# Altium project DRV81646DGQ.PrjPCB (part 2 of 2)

## Sheet DRV81646DGQ.SchDoc: DRV81646PWP
size 431 x 279 mm; VersionControl_RevNumber: 1; Date: Not shown in title block; ApprovedBy: Not shown in title block; CheckedBy: Not shown in title block; Author: Not shown in title block; CompanyName: Not shown in title block; DrawnBy: Mojtaba Afshar; Engineer: Not shown in title block; Organization: Not shown in title block; Address1: Not shown in title block; Address2: Not shown in title block; Address3: Not shown in title block; Address4: Not shown in title block; DocumentNumber: 1; Revision: 1; SheetNumber: 3; SheetTotal: 5; PageSetup: Record=PageOptions¦CenterHorizontal=True¦CenterVertical=True¦PrintScale=1.00¦XCorrection=1.00¦YCorrection=1.00¦PrintKind=0¦BorderSize=5000000¦LeftOffset=0¦BottomOffset=0¦Orientation=2¦PaperLength=1000¦PaperWidth=1000¦Scale=100¦PaperSource=15¦PrintQuality=600¦MediaType=1¦DitherType=10¦PaperKind=Letter¦PrintScaleMode=1; VersionControl_ProjFolderRevNumber: 1; VersionControl_RevNumberShort: 1; VersionControl_ProjFolderRevNumberShort: 1
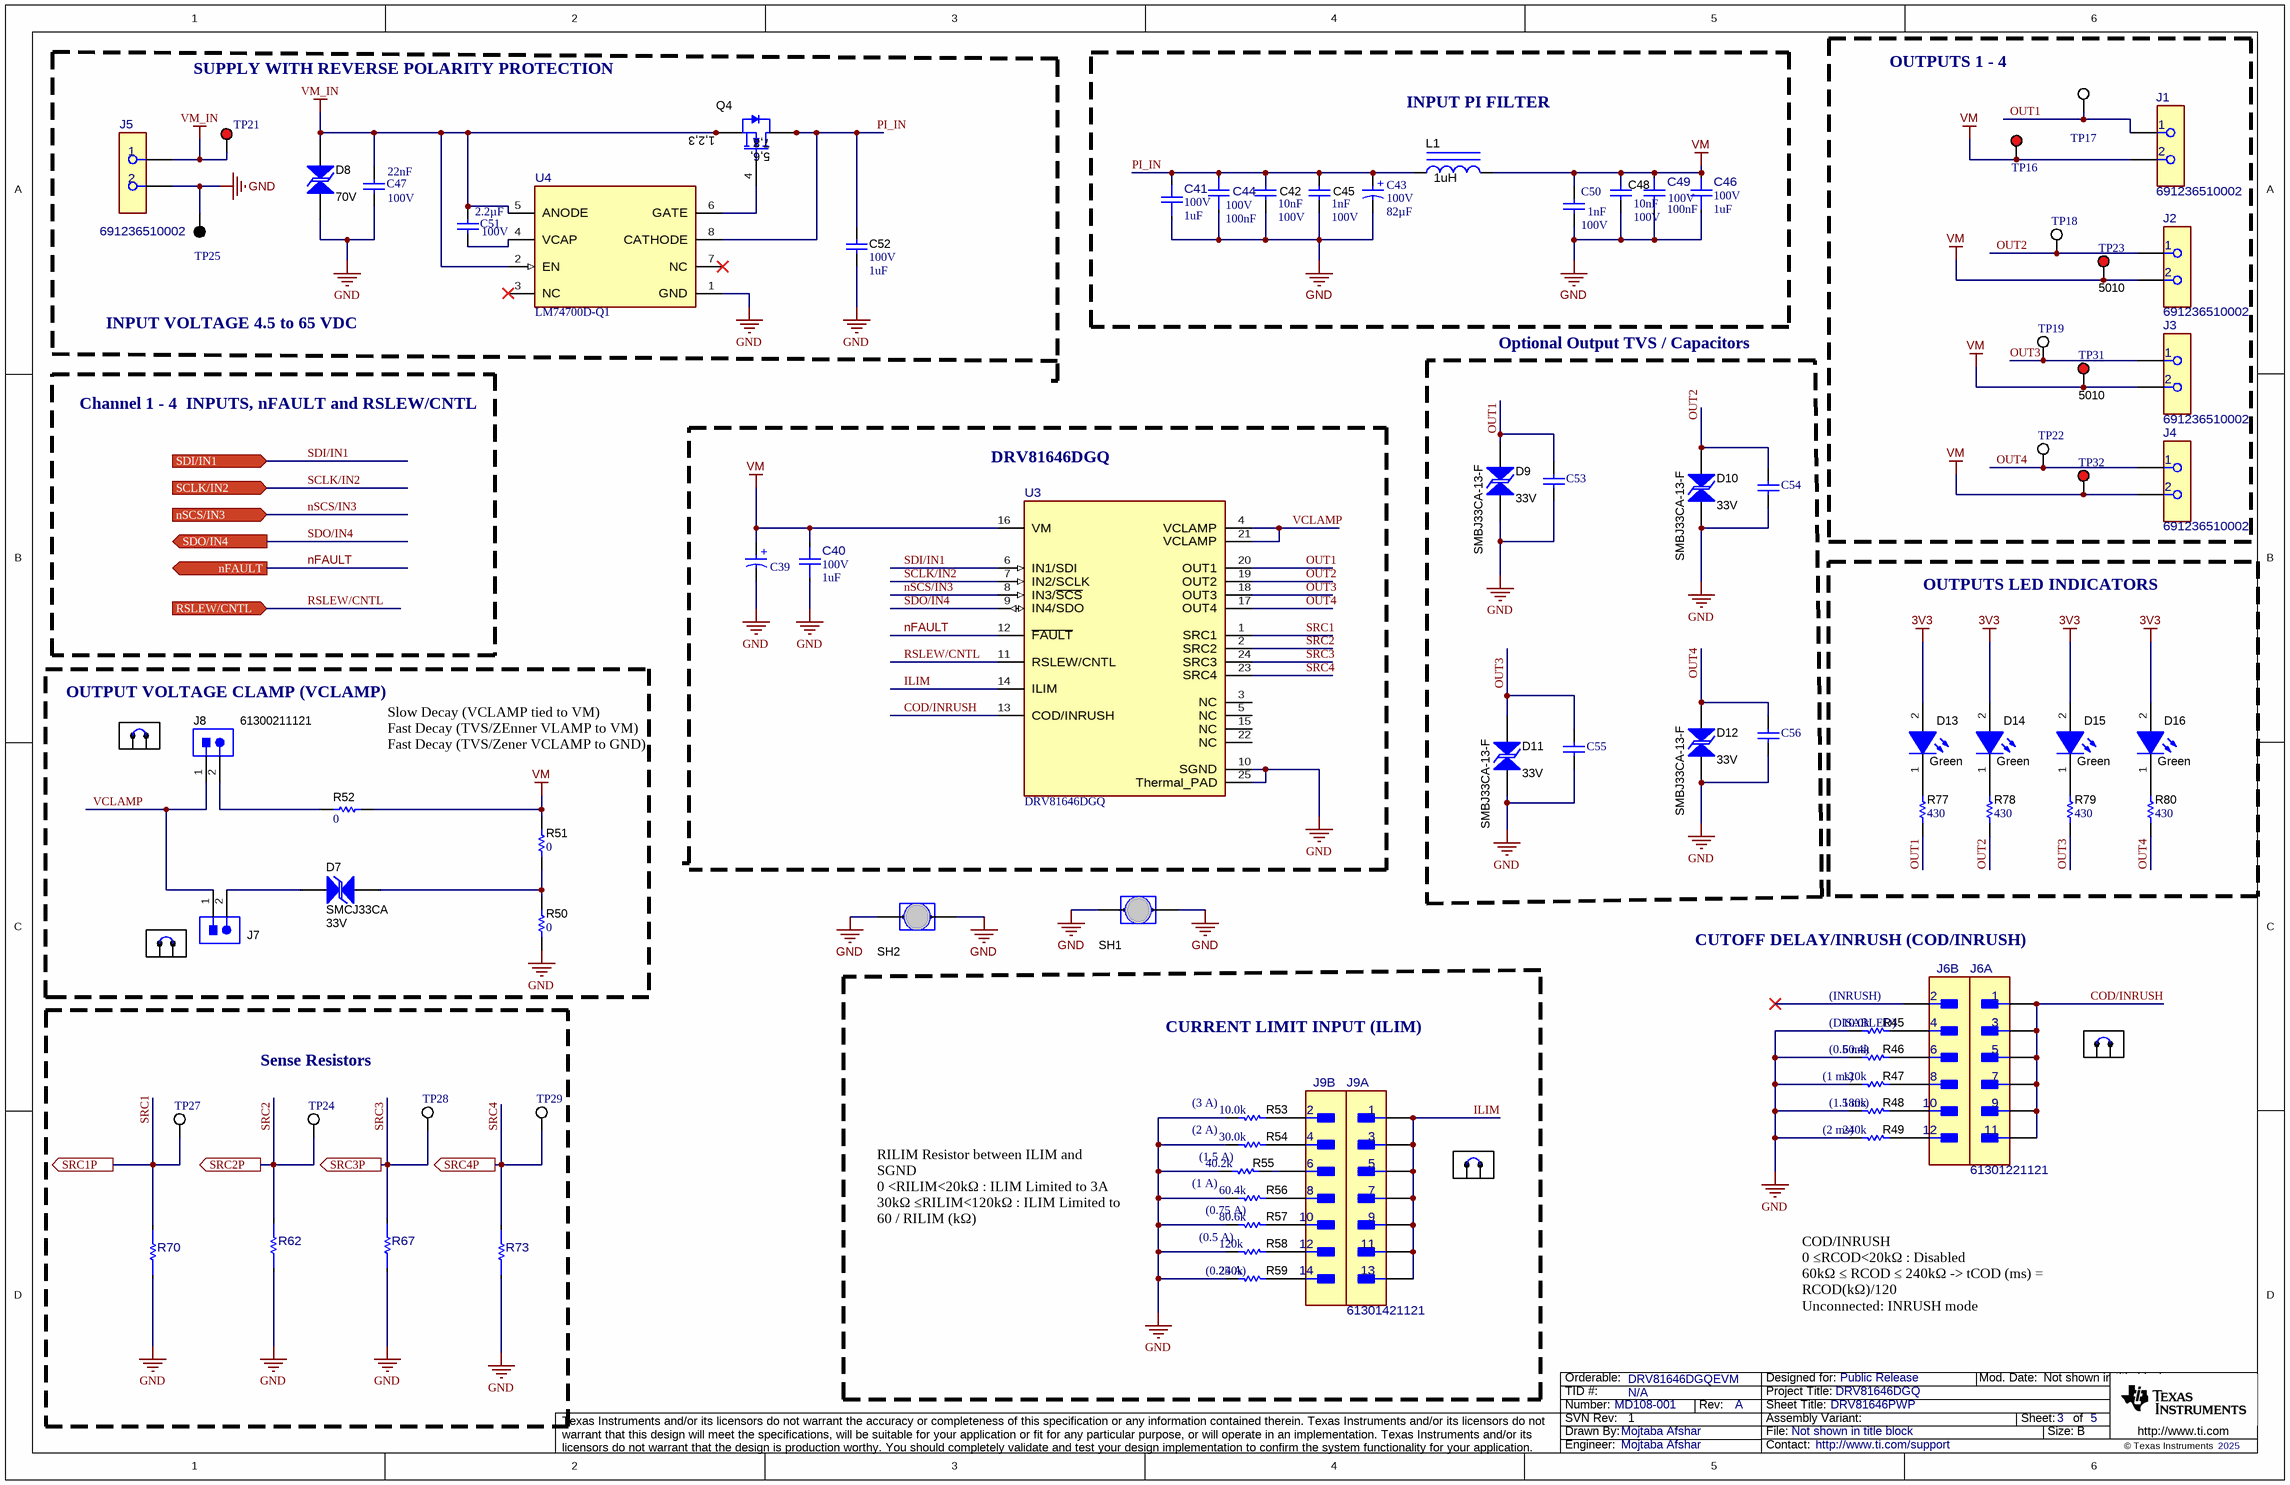
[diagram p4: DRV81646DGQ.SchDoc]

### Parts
C39  860040875002  [WCAP-ATUL_D10H12.5]  (value not drawn)
C40  VDC_V: 100V  ValueDisplayed: 1uF  [FP-885012209069_1210-MFG]  (hidden comment: 885012209069)
C41  VDC_V: 100V  ValueDisplayed: 1uF  [FP-885012209069_1210-MFG]  (hidden comment: 885012209069)
C42  Cap_F: 10nF  VDC_V: 100V  [0603]  (hidden comment: 885012206114)
C43  Cap_F: 82µF  Rated Voltage (DC): 100V  [WCAP-ATUL_D10H20]  (hidden comment: 860040875004)
C44  VDC_V: 100V  Cap_F: 100nF  [FP-885012206120_0603-MFG]  (hidden comment: 885012206120)
C45  Cap_F: 1nF  VDC_V: 100V  [0603]  (hidden comment: 06031C102KAT2A)
C46  VDC_V: 100V  ValueDisplayed: 1uF  [FP-885012209069_1210-MFG]  (hidden comment: 885012209069)
C47  Cap_F: 22nF  Rated Voltage (DC): 100V  [WCAP-CSGP_0805_L2W1.25H0.8_Reflow]  (hidden comment: 885012207124)
C48  Cap_F: 10nF  VDC_V: 100V  [0603]  (hidden comment: 885012206114)
C49  VDC_V: 100V  Cap_F: 100nF  [FP-885012206120_0603-MFG]  (hidden comment: 885012206120)
C50  Cap_F: 1nF  Rated Voltage (DC): 100V  [WCAP-CSGP_0603_L1.6W0.8H0.8_Reflow]  (hidden comment: 885012206108)
C51  Cap_F: 2.2µF  Rated Voltage (DC): 100V  [WCAP-CSST_1210_L3.2W2.5H2.5]  (hidden comment: 885382209002)
C52  VDC_V: 100V  ValueDisplayed: 1uF  [0805_HV]  (hidden comment: C2012X7S2A105K125AB)
C53  885012207124  [WCAP-CSGP_0805_L2W1.25H0.8_Reflow]  (value not drawn)
C54  885012207124  [WCAP-CSGP_0805_L2W1.25H0.8_Reflow]  (value not drawn)
C55  885012207124  [WCAP-CSGP_0805_L2W1.25H0.8_Reflow]  (value not drawn)
C56  885012207124  [WCAP-CSGP_0805_L2W1.25H0.8_Reflow]  (value not drawn)
D7  SMCJ33CA  value 33V  [SMC_Bi]
D8  value 70V  [SMB-Bi]  (hidden comment: SMBJ70CA-13-F)
D9  SMBJ33CA-13-F  value 33V  [SMB-Bi]
D10  SMBJ33CA-13-F  value 33V  [SMB-Bi]
D11  SMBJ33CA-13-F  value 33V  [SMB-Bi]
D12  SMBJ33CA-13-F  value 33V  [SMB-Bi]
D13  value Green  [WL-SMCW_GREEN]  (hidden comment: 150060VS75000)
D14  value Green  [WL-SMCW_GREEN]  (hidden comment: 150060VS75000)
D15  value Green  [WL-SMCW_GREEN]  (hidden comment: 150060VS75000)
D16  value Green  [WL-SMCW_GREEN]  (hidden comment: 150060VS75000)
J1  691236510002  [FP-691236510002_HHR2-MFG]
J2  691236510002  [FP-691236510002_HHR2-MFG]
J3  691236510002  [FP-691236510002_HHR2-MFG]
J4  691236510002  [FP-691236510002_HHR2-MFG]
J5  691236510002  [FP-691236510002_HHR2-MFG]
J6  61301221121  [FP-61301221121_HDR12-MFG]  (parts A,B of 2)
J7  61300211121  [WURTH_61300211121]  (value not drawn)
J8  61300211121  [WURTH_61300211121]
J9  61301421121  [FP-61301421121_HDR14-MFG]  (parts A,B of 2)
L1  ValueDisplayed: 1uH  [WE-HCC_1210]  (hidden comment: 7443320100)
Q4  CSD19502Q5B  [DNK0008A]  (value not drawn)
R45  ValueDisplayed: 10.0k  [0603]  (hidden comment: RC0603FR-0710KL)
R46  ValueDisplayed: 60.4k  [0603]  (hidden comment: RC0603FR-0760K4L)
R47  ValueDisplayed: 120k  [0603]  (hidden comment: RC0603FR-07120KL)
R48  ValueDisplayed: 180k  [0603]  (hidden comment: RC0603FR-07180KL)
R49  ValueDisplayed: 240k  [0603]  (hidden comment: RC0603FR-07240KL)
R50  ValueDisplayed: 0  [1206]  (hidden comment: CRCW12060000Z0EAHP)
R51  ValueDisplayed: 0  [1206]  (hidden comment: CRCW12060000Z0EAHP)
R52  ValueDisplayed: 0  [1206]  (hidden comment: CRCW12060000Z0EAHP)
R53  ValueDisplayed: 10.0k  [0603]  (hidden comment: RC0603FR-0710KL)
R54  ValueDisplayed: 30.0k  [0603]  (hidden comment: RC0603FR-0730KL)
R55  ValueDisplayed: 40.2k  [0603]  (hidden comment: RC0603FR-0740K2L)
R56  ValueDisplayed: 60.4k  [0603]  (hidden comment: RC0603FR-0760K4L)
R57  ValueDisplayed: 80.6k  [0603]  (hidden comment: RC0603FR-0780K6L)
R58  ValueDisplayed: 120k  [0603]  (hidden comment: RC0603FR-07120KL)
R59  ValueDisplayed: 240k  [0603]  (hidden comment: RC0603FR-07240KL)
R62  580060720008  [FP-580060720008_0805-MFG]  (value not drawn)
R67  580060720008  [FP-580060720008_0805-MFG]  (value not drawn)
R70  580060720008  [FP-580060720008_0805-MFG]  (value not drawn)
R73  580060720008  [FP-580060720008_0805-MFG]  (value not drawn)
R77  ValueDisplayed: 430  [0603]  (hidden comment: RC0603JR-07430RL)
R78  ValueDisplayed: 430  [0603]  (hidden comment: RC0603JR-07430RL)
R79  ValueDisplayed: 430  [0603]  (hidden comment: RC0603JR-07430RL)
R80  ValueDisplayed: 430  [0603]  (hidden comment: RC0603JR-07430RL)
SH1  Jumper_2p  [Harwin_D3082-05]  (value not drawn)
SH2  Jumper_2p  [Harwin_D3082-05]  (value not drawn)
SH-J1  60900213421  [Wurth_60900213421]  (value not drawn)
SH-J10  60900213421  [Wurth_60900213421]  (value not drawn)
SH-J11  60900213421  [Wurth_60900213421]  (value not drawn)
SH-J12  60900213421  [Wurth_60900213421]  (value not drawn)
TP16  5010  [Keystone5010]  (value not drawn)
TP17  5012  [Keystone5012]  (value not drawn)
TP18  5012  [Keystone5012]  (value not drawn)
TP19  5012  [Keystone5012]  (value not drawn)
TP21  5010  [Keystone5010]  (value not drawn)
TP22  5012  [Keystone5012]  (value not drawn)
TP23  5010  [Keystone5010]
TP24  5002  [Keystone5002]  (value not drawn)
TP25  5011  [Keystone5011]  (value not drawn)
TP27  5002  [Keystone5002]  (value not drawn)
TP28  5002  [Keystone5002]  (value not drawn)
TP29  5002  [Keystone5002]  (value not drawn)
TP31  5010  [Keystone5010]
TP32  5010  [Keystone5010]  (value not drawn)
U3  DRV81646DGQ  [DGQ0024A-MFG]
U4  LM74700D-Q1  [D0008A-MFG]

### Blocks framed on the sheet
INPUT PI FILTER: C41-C46 C48-C50 L1
Optional Output TVS / Capacitors: C53-C56 D9-D12
OUTPUTS LED INDICATORS: D13-D16 R77-R80
CURRENT LIMIT INPUT (ILIM): J9 R53-R59 SH-J11
Sense Resistors: R62 R67 R70 R73 TP24 TP27-TP29

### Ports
nFAULT (out), nSCS/IN3 (in), RSLEW/CNTL (in), SCLK/IN2 (in), SDI/IN1 (in), SDO/IN4 (out), SRC1P (out), SRC2P (out), SRC3P (out), SRC4P (out)

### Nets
3V3: D13.2(A) D14.2(A) D15.2(A) D16.2(A)
GND: C39.2(N) C40.1 C41.1 C42.1 C43.2(N) C44.1 C45.2 C46.1 C47.1 C48.1 C49.1 C50.1 C52.2 C53.1 C54.1 C55.1 C56.1 D8.1 D9.1 D10.1 D11.1 D12.1 J5.2 R45.1 R46.1 R47.1 R48.1 R49.1 R50.1 R53.1 R54.1 R55.1 R56.1 R57.1 R58.1 R59.1 R62.1 R67.1 R70.1 R73.1 SH1.1 SH1.2 SH2.1 SH2.2 TP25.1 U3.10(SGND) U3.25(Thermal_PAD) U4.1(GND)
VM: C39.1(P) C40.2 C46.2 C48.2 C49.2 C50.2 J1.2 J2.2 J3.2 J4.2 L1.2 R51.2 R52.2 TP16.1 TP23.1 TP31.1 TP32.1 U3.16(VM)
VM_IN: C47.2 C51.2 D8.2 J5.1 Q4.1(S) Q4.2(S) Q4.3(S) TP21.1 U4.2(EN) U4.5(ANODE)
COD/INRUSH: J6.1 J6.3 J6.5 J6.7 J6.9 J6.11 U3.13(COD/INRUSH)
ILIM: J9.1 J9.3 J9.5 J9.7 J9.9 J9.11 J9.13 U3.14(ILIM)
nFAULT: U3.12(~{FAULT}) ; port nFAULT
nSCS/IN3: U3.8(IN3/~{SCS}) ; port nSCS/IN3
OUT1: C53.2 D9.2 J1.1 R77.1 TP17.1 U3.20(OUT1)
OUT2: C54.2 D10.2 J2.1 R78.1 TP18.1 U3.19(OUT2)
OUT3: C55.2 D11.2 J3.1 R79.1 TP19.1 U3.18(OUT3)
OUT4: C56.2 D12.2 J4.1 R80.1 TP22.1 U3.17(OUT4)
PI_IN: C41.2 C42.2 C43.1(P) C44.2 C45.1 C52.1 L1.1 Q4.5(D) Q4.6(D) Q4.7(D) Q4.8(D) Q4.9(D) U4.8(CATHODE)
RSLEW/CNTL: U3.11(RSLEW/CNTL) ; port RSLEW/CNTL
SCLK/IN2: U3.7(IN2/SCLK) ; port SCLK/IN2
SDI/IN1: U3.6(IN1/SDI) ; port SDI/IN1
SDO/IN4: U3.9(IN4/SDO) ; port SDO/IN4
SRC1: R70.2 TP27.1 U3.1(SRC1) ; port SRC1P
SRC2: R62.2 TP24.1 U3.2(SRC2) ; port SRC2P
SRC3: R67.2 TP28.1 U3.24(SRC3) ; port SRC3P
SRC4: R73.2 TP29.1 U3.23(SRC4) ; port SRC4P
VCLAMP: J7.1 J8.1 U3.4(VCLAMP) U3.21(VCLAMP)
NetC51_1: C51.1 U4.4(VCAP)
NetD7_1: D7.1 J7.2
NetD7_2: D7.2 R50.2 R51.1
NetD13_1: D13.1(K) R77.2
NetD14_1: D14.1(K) R78.2
NetD15_1: D15.1(K) R79.2
NetD16_1: D16.1(K) R80.2
NetJ6_4: J6.4 R45.2
NetJ6_6: J6.6 R46.2
NetJ6_8: J6.8 R47.2
NetJ6_10: J6.10 R48.2
NetJ6_12: J6.12 R49.2
NetJ8_2: J8.2 R52.1
NetJ9_2: J9.2 R53.2
NetJ9_4: J9.4 R54.2
NetJ9_6: J9.6 R55.2
NetJ9_8: J9.8 R56.2
NetJ9_10: J9.10 R57.2
NetJ9_12: J9.12 R58.2
NetJ9_14: J9.14 R59.2
NetQ4_4: Q4.4(G) U4.6(GATE)

Not connected (* = marked no-connect by the designer): J6 2*; U3 3(NC) 5(NC) 15(NC) 22(NC); U4 3(NC)* 7(NC)*

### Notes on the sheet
- SUPPLY WITH REVERSE POLARITY PROTECTION
- OUTPUTS 1 - 4
- INPUT VOLTAGE 4.5 to 65 VDC
- Channel 1 - 4  INPUTS, nFAULT and RSLEW/CNTL
- DRV81646DGQ
- OUTPUT VOLTAGE CLAMP (VCLAMP)
- Slow Decay (VCLAMP tied to VM)
  Fast Decay (TVS/ZEnner VLAMP to VM)
  Fast Decay (TVS/Zener VCLAMP to GND)
- CUTOFF DELAY/INRUSH (COD/INRUSH)
- (DISABLED)
- (INRUSH)
- (3 A)
- (1 ms)
- (0.5 ms)
- (1.5 ms)
- (2 A)
- (1.5 A)
- (2 ms)
- RILIM Resistor between ILIM and SGND
  0 <RILIM<20kΩ : ILIM Limited to 3A
  30kΩ ≤RILIM<120kΩ : ILIM Limited to 60 / RILIM (kΩ)
  120kΩ ≤RILIM : ILIM Limited to 60 / RILIM (kΩ), Linearity is not guaranteed.
- (1 A)
- (0.5 A)
- (0.75 A)
- (0.25 A)
- COD/INRUSH
  0 ≤RCOD<20kΩ : Disabled
  60kΩ ≤ RCOD ≤ 240kΩ -> tCOD (ms) = RCOD(kΩ)/120
  Unconnected: INRUSH mode

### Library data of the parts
C39 = CMP-0102580-1: WCAP-ATUL Aluminum Electrolytic Capacitor, Radial, THT, D10 x H12.5mm, 47µF, 100V; Manufacturer: Wurth Elektronik; Capacitance Tolerance: 20%; Dissipation Factor: 9%; Endurance: 7000h; Leakage Current: 47uA; Ripple Current: 400mA; Technical Reference: ATDF125470M100DSPA9G000
C40 C41 C46 = CMP-0097312-1: 1 µF ±10% 100V Ceramic Capacitor X7R 1210 (3225 Metric); Manufacturer: Wurth Electronics; AEC Qualified: No; SizeZ_mm: 2.2mm; Cap_F: 1µF; Value: 1µF; TempCo: 15%
C42 C48 = CMP-0079993-1: CAP, CERM, 0.01 µF, 100 V,+/- 10%, X7R, 0603; Manufacturer: Wurth Elektronik; TaMin_C: -55°C; Polarized: N; SizeAreaWB_mm2: 4.68; U/M: EA; Value: 0.01uF; TaMax_C: 105°C; SizeZ_mm: 1; SizeX_mm: 1.6; SizeY_mm: 0.8; SizeArea_mm2: 1.28; AEC Category: Q200; ValueDisplayed: 0.01µF
C43 = CMP-0102582-1: WCAP-ATUL Aluminum Electrolytic Capacitor, Radial, THT, D10 x H20mm, 82µF, 100V; Manufacturer: Wurth Elektronik; Capacitance Tolerance: 20%; Dissipation Factor: 9%; Endurance: 7000h; Leakage Current: 82uA; Ripple Current: 600mA; Technical Reference: ATDF200820M100DSPAAG000
C44 C49 = CMP-0097294-1: 0.1 µF ±10% 100V Ceramic Capacitor X7R 0603 (1608 Metric); Manufacturer: Wurth Electronics; TempCo: 15%; SizeZ_mm: 0.87mm; Value: 100nF; AEC Qualified: No
C45 = CMP-0006724-5: CAP, CERM, 1000 pF, 100 V, +/- 10%, X7R, 0603; Manufacturer: AVX; TaMin_C: -55°C; ESR_ohm: 2.76d; Polarized: N; SizeAreaWB_mm2: 4.68; Value1: 0.276 ohm; U/M: EA; Value: 1000pF; TaMax_C: 125°C; SizeZ_mm: 1; SizeX_mm: 1.6; SizeY_mm: 0.8; SizeArea_mm2: 1.28; AEC Category: Q200
C47 = CMP-0119538-1: WCAP-CSGP Multilayer Ceramic Chip Capacitor, General Purpose, size 0805, X7R, 22nF, 100VDC; Manufacturer: Wurth Elektronik; Capacitance Tolerance: +/-10%; Case/Size Code: 0805; Dissipation Factor: 2.5%; Insulation Resistance: 4.5GOhm; Technical Reference: X7R0805223K100DFCT10000
C50 = CMP-0119409-1: WCAP-CSGP Multilayer Ceramic Chip Capacitor, General Purpose, size 0603, X7R, 1nF, 100VDC; Manufacturer: Wurth Elektronik; Capacitance Tolerance: +/-10%; Case/Size Code: 0603; Dissipation Factor: 2.5%; Insulation Resistance: 10GOhm; Technical Reference: X7R0603102K100DFCT10000
C51 = CMP-0119921-1: WCAP-CSST Multilayer Ceramic Chip Capacitor, Soft Termination, size 1210, X7R Class II, 2.2µF, 100VDC; Manufacturer: Wurth Elektronik; Capacitance Tolerance: +/-10%; Case/Size Code: 1210; Dissipation Factor: 5%; Insulation Resistance: 0.05GOhm; Technical Reference: X7R1210225K100DFCT1S000
C52 = CMP-0007891-2: CAP, CERM, 1 uF, 100 V, +/- 10%, X7S, 0805; Manufacturer: TDK; TaMin_C: -55°C; ESR_ohm: 8.255m; Polarized: N; SizeAreaWB_mm2: 6.75; Value1: 0.008255 ohm; U/M: EA; Value: 1uF; TaMax_C: 125°C; SizeZ_mm: 1.45; SizeX_mm: 2; SizeY_mm: 1.25; Cap_Case: 0805; SizeArea_mm2: 2.5; Cap_F: 1µF; IRMS_A: 2.27442A; AEC Category: Q200
C53-C56 = CMP-0119538-1: WCAP-CSGP Multilayer Ceramic Chip Capacitor, General Purpose, size 0805, X7R, 22nF, 100VDC; Manufacturer: Wurth Elektronik; Capacitance Tolerance: +/-10%; Case/Size Code: 0805; Dissipation Factor: 2.5%; Insulation Resistance: 4.5GOhm; Rated Voltage (DC): 100V; Technical Reference: X7R0805223K100DFCT10000
D7 = CMP-0005695-3: Diode, TVS, Bi, 33 V, SMC; Manufacturer: Bourns; SizeZ_mm: 2.6; Ppk: 1.5kW; Value1: 1500W; AEC Category: Q101; SizeArea_mm2: 50.5686; SizeX_mm: 8.13; SizeAreaWB_mm2: 83.2686; SizeY_mm: 6.22
D8 = CMP-0005587-3: Diode, TVS, Bi, 70 V, SMB; Manufacturer: Diodes Inc.; AEC Category: Q101; SizeX_mm: 5.6; SizeY_mm: 3.81; Ppk: 600W; SizeZ_mm: 2.6; SizeArea_mm2: 21.336; SizeAreaWB_mm2: 44.156
D9-D12 = CMP-0005564-3: Diode, TVS, Bi, 33 V, SMB; Manufacturer: Diodes Inc.; SizeX_mm: 5.6; Ppk: 600W; SizeAreaWB_mm2: 44.156; SizeZ_mm: 2.6; SizeArea_mm2: 21.336; SizeY_mm: 3.81; AEC Category: Q101
D13-D16 = CMP-0002894-2: LED, Green, SMD; Manufacturer: Wurth Elektronik; Type: AlInGaP; Value2: 2V; Io_A: 20mA; Value1: W
J1-J5 = CMP-0121282-1: 2 Position Wire to Board Terminal Block Horizontal with Board 0.200" (5.08mm) Through Hole; Manufacturer: Wurth Electronics; Current_A: 20A; Row_Count: 1; Voltage_V: 300V; AEC Qualified: No; Conn Gender: Female; Is Female: yes; Max Wire Gauge: 12; Min Wire Gauge: 30; SizeZ_mm: 18.1mm
J6 = CMP-0092423-1: THT Vertical Pin Header WR-PHD, Pitch 2.54 mm, Dual Row, 12 pins; Manufacturer: Wurth Electronics; Is Female: no; DUT-Pitch_mm: 2.54mm; Row_Count: 2; Current_A: 3A; Voltage_V: 250V; Conn Gender: Male; Conn Orientation: Straight; SizeZ_mm: 8.89mm; ContactFinish: Gold
J7 J8 = CMP-0054794-2: Header, 2.54 mm, 2x1, Gold, TH; Manufacturer: Wurth Elektronik; Shrouded: N; Gender: Male; Green_REACh: Passed; Pitch_mm: 2.54; Green_Lifecycle: Active; Row_Count: 1; Cert_UL: Y
J9 = CMP-0097334-1: Connector Header Through Hole 14 position 0.100" (2.54mm); Manufacturer: Wurth Electronics; AEC Qualified: No; Conn Gender: Male; Current_A: 3A; Voltage_V: 250V; ContactFinish: Gold; Row_Count: 2; SizeZ_mm: 8.89mm; Conn Orientation: Straight
L1 = CMP-0063986-1: Inductor, Shielded Drum Core, Ferrite, 1 uH, 24 A, 0.0012 ohm, SMD; Manufacturer: Wurth Elektronik; Isat: 32A @ 30% inductance drop; Irms: 24A @ 50C rise; Green_Lifecycle: Active; SizeAreaWB_mm2: 188.94; DCR_ohm: 1.2m; Green_REACh: Passed; Value: 1uH; Imax_A: 24A; SizeZ_mm: 10; SizeX_mm: 12.1; SizeY_mm: 11.4; SizeArea_mm2: 137.94; Ind_H: 1µH; AEC Category: Q200
Q4 = CMP-0000915-2: MOSFET, N-CH, 80 V, 100 A, DNK0008A (VSON-CLIP-8); Alternate Manufacturer: None; Manufacturer: Texas Instruments; SizeZ_mm: 1; ChType: N; Value2: 48 nC; VdsMax_V: 80V; SizeX_mm: 6; SizeY_mm: 5; Vgs_V: 20V; Value: 80V; SizeArea_mm2: 30; AEC Category: Q101; IdsMax_A: 100A; SizeAreaWB_mm2: 56; U/M: EA; QgTyp_nC: 48
R45 R53 = CMP-0022746-5: RES, 10.0 k, 1%, 0.1 W, 0603; Manufacturer: Yageo; Power_W: 100mW; TempCo: 100 ppm/C; Value_Code: 10k0; Value: 10.0k; EIA_Code: E96; Res_ohm: 10k; SizeX_mm: 1.6; SizeY_mm: 0.8; SizeZ_mm: 1; Value2: 0.1W; SizeArea_mm2: 1.28; AEC Qualified: N; VDC_V: 75V; AEC Category: Q200; SizeAreaWB_mm2: 4.68
R46 R56 = CMP-0023212-5: RES, 60.4 k, 1%, 0.1 W, 0603; Manufacturer: Yageo; Power_W: 100mW; TempCo: 100 ppm/C; Value_Code: 60k4; Value: 60.4k; EIA_Code: E96; SizeX_mm: 1.6; SizeY_mm: 0.8; SizeZ_mm: 1; Value2: 0.1W; SizeArea_mm2: 1.28; AEC Qualified: N; VDC_V: 75V; AEC Category: Q200; SizeAreaWB_mm2: 4.68
R47 R58 = CMP-0022768-4: RES, 120 k, 1%, 0.1 W, 0603; Manufacturer: Yageo; Power_W: 100mW; TempCo: 100 ppm/C; Value: 120k; SizeX_mm: 1.6; SizeY_mm: 0.8; SizeZ_mm: 1; Value2: 0.1W; SizeArea_mm2: 1.28; AEC Qualified: N; VDC_V: 75V; AEC Category: Q200; SizeAreaWB_mm2: 4.68
R48 = CMP-0022844-4: RES, 180 k, 1%, 0.1 W, 0603; Manufacturer: Yageo; Power_W: 100mW; TempCo: 100 ppm/C; Value: 180k; SizeX_mm: 1.6; SizeY_mm: 0.8; SizeZ_mm: 1; Value2: 0.1W; SizeArea_mm2: 1.28; AEC Qualified: N; VDC_V: 75V; AEC Category: Q200; SizeAreaWB_mm2: 4.68
R49 R59 = CMP-0022937-4: RES, 240 k, 1%, 0.1 W, 0603; Manufacturer: Yageo; Power_W: 100mW; TempCo: 100 ppm/C; Value: 240k; SizeX_mm: 1.6; SizeY_mm: 0.8; SizeZ_mm: 1; Value2: 0.1W; SizeArea_mm2: 1.28; AEC Qualified: N; VDC_V: 75V; AEC Category: Q200; SizeAreaWB_mm2: 4.68
R50-R52 = CMP-0086176-1: RES, 0, 0.75 W, AEC-Q200 Grade 0, 1206; Manufacturer: Vishay-Dale; Value: 0; SizeY_mm: 1.6; SizeX_mm: 3.2; Tolerance_%: 0%; SizeArea_mm2: 5.12; EIA_Code: E96; SizeAreaWB_mm2: 10.92; Power_W: 750mW; AEC Qualified: Y; SizeZ_mm: 1.35; Value2: 0.75W; AEC Category: Q200; VDC_V: 200V
R54 = CMP-0023020-5: RES, 30.0 k, 1%, 0.1 W, 0603; Manufacturer: Yageo; Power_W: 100mW; TempCo: 100 ppm/C; Value_Code: 30k0; Value: 30.0k; Res_ohm: 30k; SizeX_mm: 1.6; SizeY_mm: 0.8; SizeZ_mm: 1; Value2: 0.1W; SizeArea_mm2: 1.28; AEC Qualified: N; VDC_V: 75V; AEC Category: Q200; SizeAreaWB_mm2: 4.68
R55 = CMP-0023098-5: RES, 40.2 k, 1%, 0.1 W, 0603; Manufacturer: Yageo; Power_W: 100mW; TempCo: 100 ppm/C; Value_Code: 40k2; Value: 40.2k; EIA_Code: E96; SizeX_mm: 1.6; SizeY_mm: 0.8; SizeZ_mm: 1; Value2: 0.1W; SizeArea_mm2: 1.28; AEC Qualified: N; VDC_V: 75V; AEC Category: Q200; SizeAreaWB_mm2: 4.68
R57 = CMP-0023285-5: RES, 80.6 k, 1%, 0.1 W, 0603; Manufacturer: Yageo; Power_W: 100mW; TempCo: 100 ppm/C; Value_Code: 80k6; EIA_Code: E96; SizeX_mm: 1.6; SizeY_mm: 0.8; SizeZ_mm: 1; Value2: 0.1W; Value: 80.6k; SizeArea_mm2: 1.28; AEC Qualified: N; VDC_V: 75V; AEC Category: Q200; SizeAreaWB_mm2: 4.68
R62 R67 R70 R73 = CMP-0041688-1: 10 mOhms ±1% 0.5W, 1/2W Chip Resistor 0805 (2012 Metric) Current Sense Thick Film; Manufacturer: Wurth Electronics; AEC Qualified: No; Power_W: 500mW; Res_ohm: 10m; SizeZ_mm: 0.32mm; TempCo: 100ppm/°C; VDC_V: 70.7mV; Value: 10m
R77-R80 = CMP-0025922-5: RES, 430, 5%, 0.1 W, 0603; Manufacturer: Yageo; Power_W: 100mW; TempCo: 100 ppm/C; Value_Code: 430R; Value: 430; EIA_Code: E24; SizeX_mm: 1.6; SizeY_mm: 0.8; SizeZ_mm: 1; Value2: 0.1W; SizeArea_mm2: 1.28; AEC Qualified: N; VDC_V: 75V; AEC Category: Q200; SizeAreaWB_mm2: 4.68
SH1 SH2 = CMP-0075110-1: 1mm Uninsulated Shorting Plug, 10.16mm spacing, TH; PartNumber: D3082-05; Manufacturer: Harwin; CNHeader: False; CompType: Jumper Wire; Green_Lifecycle: Active; Green_REACh: Passed
SH-J1 SH-J10-SH-J12 = CMP-0003761-2: Shunt, 2.54mm, Gold, Black; Manufacturer: Wurth Elektronik
TP16 TP23 TP31 TP32 = CMP-0055147-2: Test Point, Multipurpose, Red, TH; Manufacturer: Keystone Electronics; CT: TRUE; ContactFinish: Silver; Green_Lifecycle: Active; CNHeader: FALSE; Green_REACh: Passed
TP17-TP19 TP22 = CMP-0055149-2: Test Point, Multipurpose, White, TH; Manufacturer: Keystone Electronics; ContactFinish: Silver; CT: TRUE; CNHeader: FALSE; Green_Lifecycle: Active; Green_REACh: Passed
TP21 = CMP-0055147-2: Test Point, Multipurpose, Red, TH; Manufacturer: Keystone Electronics; CNHeader: FALSE; Green_Lifecycle: Active; Green_REACh: Passed; ContactFinish: Silver; CT: TRUE
TP24 TP27-TP29 = CMP-0055139-2: Test Point, Miniature, White, TH; Manufacturer: Keystone Electronics; ContactFinish: Silver; Green_REACh: Passed; CT: TRUE; Green_Lifecycle: Active; CNHeader: FALSE
TP25 = CMP-0055148-2: Test Point, Multipurpose, Black, TH; Manufacturer: Keystone Electronics; CNHeader: FALSE; Green_Lifecycle: Active; Green_REACh: Passed; ContactFinish: Silver; CT: TRUE
U3 = CMP-0125014-1: Quad Low-Side Switches, HVSSOP24; Manufacturer: Texas Instruments; SizeZ_mm: 1.1mm; AEC Qualified: No; Max Supply Voltage: 65V; Min Supply Voltage: 4.5V; Nominal Supply Current: 3mA; Number Of Outputs: 4; Standoff Height: 0.05mm; TaMax_C: +125°C; TaMin_C: -40°C; TJmax_C: +150°C
U4 = CMP-0125797-1: Manufacturer: Texas Instruments; SizeZ_mm: 1.75mm; Standoff Height: 0.11mm

## Sheet DRV81646DGQ_ADC.SchDoc: ADC
size 431 x 279 mm; Date: Not shown in title block; ApprovedBy: Not shown in title block; CheckedBy: Not shown in title block; Author: Not shown in title block; CompanyName: Not shown in title block; DrawnBy: Mojtaba Afshar; Engineer: Not shown in title block; Organization: Not shown in title block; Address1: Not shown in title block; Address2: Not shown in title block; Address3: Not shown in title block; Address4: Not shown in title block; DocumentNumber: 2; Revision: Use project parameter SCH_Rev; SheetNumber: 4; SheetTotal: 5; PageSetup: Record=PageOptions¦CenterHorizontal=True¦CenterVertical=True¦PrintScale=1.00¦XCorrection=1.00¦YCorrection=1.00¦PrintKind=0¦BorderSize=5000000¦LeftOffset=0¦BottomOffset=0¦Orientation=2¦PaperLength=1000¦PaperWidth=1000¦Scale=100¦PaperSource=15¦PrintQuality=600¦MediaType=1¦DitherType=10¦PaperKind=Letter¦PrintScaleMode=1
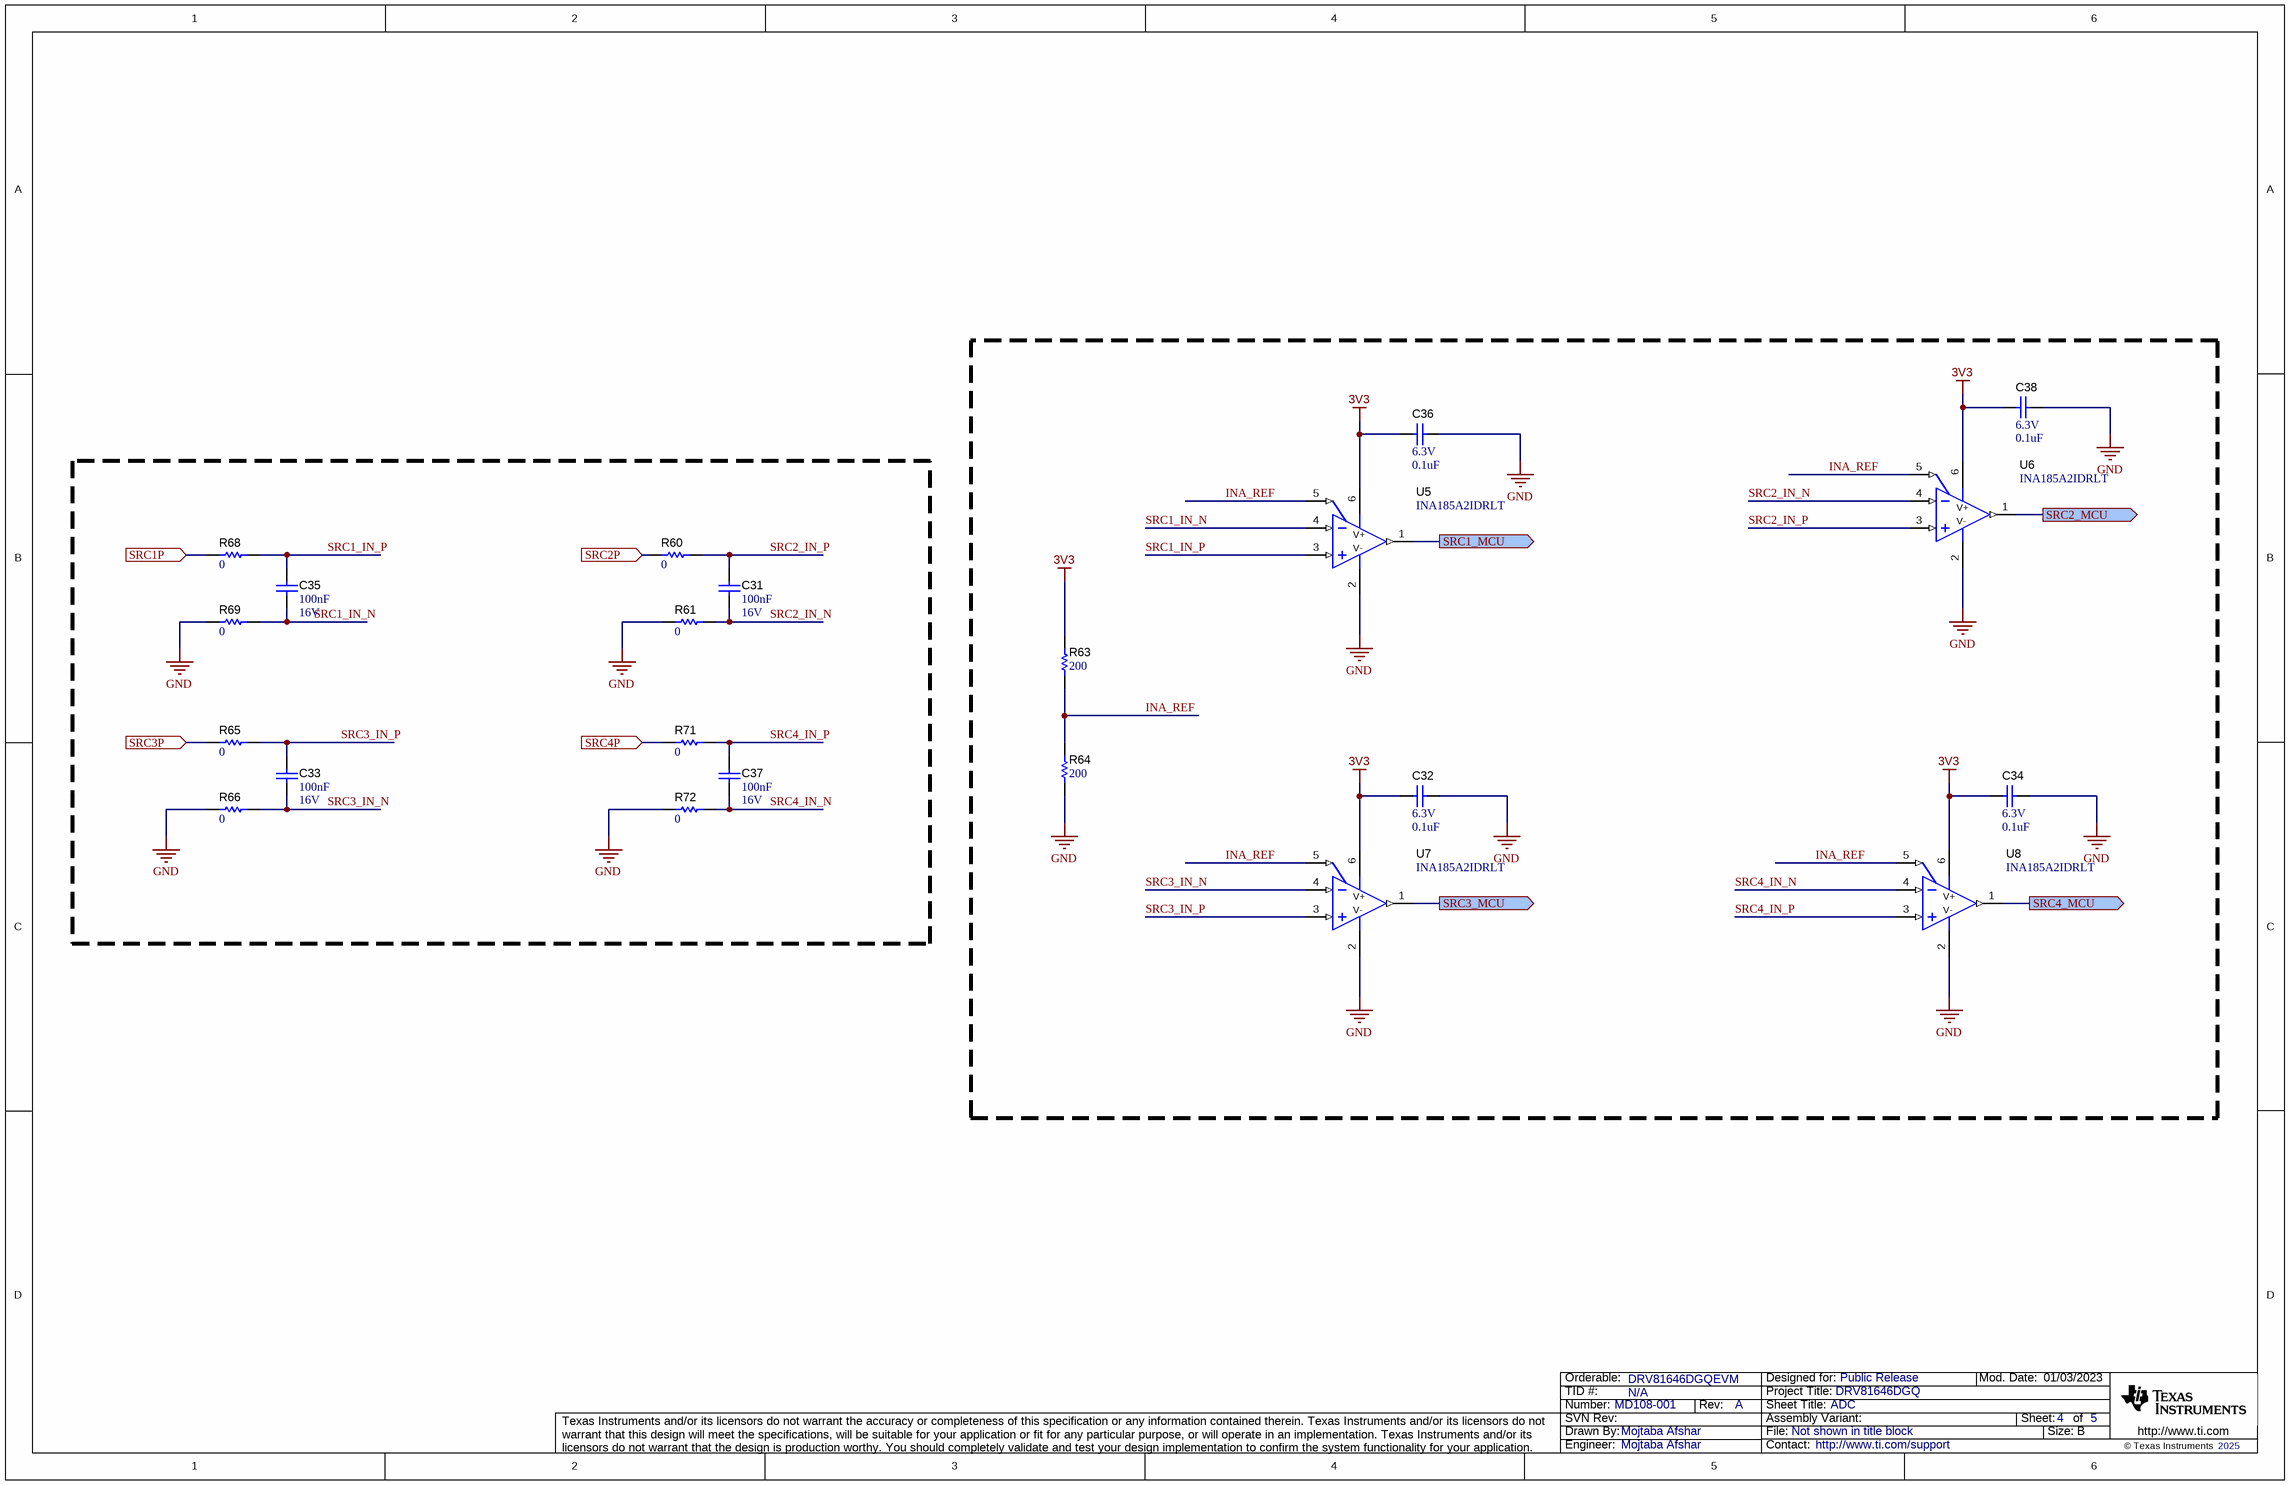
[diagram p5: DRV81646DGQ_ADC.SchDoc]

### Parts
C31  Cap_F: 100nF  VDC_V: 16V  [0603]  (hidden comment: 885012206046)
C32  VDC_V: 6.3V  ValueDisplayed: 0.1uF  [0402]  (hidden comment: 885012105001)
C33  Cap_F: 100nF  VDC_V: 16V  [0603]  (hidden comment: 885012206046)
C34  VDC_V: 6.3V  ValueDisplayed: 0.1uF  [0402]  (hidden comment: 885012105001)
C35  Cap_F: 100nF  VDC_V: 16V  [0603]  (hidden comment: 885012206046)
C36  VDC_V: 6.3V  ValueDisplayed: 0.1uF  [0402]  (hidden comment: 885012105001)
C37  Cap_F: 100nF  VDC_V: 16V  [0603]  (hidden comment: 885012206046)
C38  VDC_V: 6.3V  ValueDisplayed: 0.1uF  [0402]  (hidden comment: 885012105001)
R60  ValueDisplayed: 0  [0603]  (hidden comment: ERJ-3GEY0R00V)
R61  ValueDisplayed: 0  [0603]  (hidden comment: ERJ-3GEY0R00V)
R63  ValueDisplayed: 200  [0603]  (hidden comment: RC0603FR-07200RL)
R64  ValueDisplayed: 200  [0603]  (hidden comment: RC0603FR-07200RL)
R65  ValueDisplayed: 0  [0603]  (hidden comment: ERJ-3GEY0R00V)
R66  ValueDisplayed: 0  [0603]  (hidden comment: ERJ-3GEY0R00V)
R68  ValueDisplayed: 0  [0603]  (hidden comment: ERJ-3GEY0R00V)
R69  ValueDisplayed: 0  [0603]  (hidden comment: ERJ-3GEY0R00V)
R71  ValueDisplayed: 0  [0603]  (hidden comment: ERJ-3GEY0R00V)
R72  ValueDisplayed: 0  [0603]  (hidden comment: ERJ-3GEY0R00V)
U5  INA185A2IDRLT  [DRL0006A]
U6  INA185A2IDRLT  [DRL0006A]
U7  INA185A2IDRLT  [DRL0006A]
U8  INA185A2IDRLT  [DRL0006A]

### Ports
SRC1_MCU (out), SRC1P (in), SRC2_MCU (out), SRC2P (in), SRC3_MCU (out), SRC3P (in), SRC4_MCU (out), SRC4P (in)

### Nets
3V3: C32.2 C34.2 C36.2 C38.2 R63.2 U5.6(V+) U6.6(V+) U7.6(V+) U8.6(V+)
GND: C32.1 C34.1 C36.1 C38.1 R61.1 R64.1 R66.1 R69.1 R72.1 U5.2(V-) U6.2(V-) U7.2(V-) U8.2(V-)
INA_REF: R63.1 R64.2 U5.5(REF) U6.5(REF) U7.5(REF) U8.5(REF)
SRC1: R68.1 ; port SRC1P
SRC1_ADC_MCU: U5.1(OUT) ; port SRC1_MCU
SRC1_IN_N: C35.2 R69.2 U5.4(IN-)
SRC1_IN_P: C35.1 R68.2 U5.3(IN+)
SRC2: R60.1 ; port SRC2P
SRC2_ADC_MCU: U6.1(OUT) ; port SRC2_MCU
SRC2_IN_N: C31.2 R61.2 U6.4(IN-)
SRC2_IN_P: C31.1 R60.2 U6.3(IN+)
SRC3: R65.1 ; port SRC3P
SRC3_ADC_MCU: U7.1(OUT) ; port SRC3_MCU
SRC3_IN_N: C33.2 R66.2 U7.4(IN-)
SRC3_IN_P: C33.1 R65.2 U7.3(IN+)
SRC4: R71.1 ; port SRC4P
SRC4_ADC_MCU: U8.1(OUT) ; port SRC4_MCU
SRC4_IN_N: C37.2 R72.2 U8.4(IN-)
SRC4_IN_P: C37.1 R71.2 U8.3(IN+)

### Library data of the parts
C31 C33 C35 C37 = CMP-0006829-4: CAP, CERM, 0.1 uF, 16 V, +/- 10%, X7R, 0603; Manufacturer: Wurth Elektronik; TaMin_C: -55°C; Polarized: N; SizeAreaWB_mm2: 4.68; Value1: Unknown; U/M: EA; Value: 0.1uF; TaMax_C: 125°C; SizeZ_mm: 1; SizeX_mm: 1.6; SizeY_mm: 0.8; SizeArea_mm2: 1.28; AEC Category: Q200
C32 C34 C36 C38 = CMP-0006219-2: CAP, CERM, 0.1 uF, 6.3 V, +/- 20%, X5R, 0402; Manufacturer: Wurth Elektronik; TaMin_C: -55°C; Polarized: N; SizeAreaWB_mm2: 3; Value1: Unknown; U/M: EA; Value: 0.1uF; TaMax_C: 85°C; SizeZ_mm: 0.6; SizeX_mm: 1; SizeY_mm: 0.5; Cap_F: 100nF; AEC Category: Q200
R60 R61 R65 R66 R68 R69 R71 R72 = CMP-0025874-4: RES, 0, 5%, 0.1 W, AEC-Q200 Grade 0, 0603; Manufacturer: Panasonic; Power_W: 100mW; TempCo: 600 ppm/C; Value_Code: 0000; Value: 0; EIA_Code: E24; SizeX_mm: 1.6; SizeY_mm: 0.8; SizeZ_mm: 1; Value2: 0.1W; SizeArea_mm2: 1.28; AEC Qualified: Y; VDC_V: 50V; AEC Category: Q200; SizeAreaWB_mm2: 4.68
R63 R64 = CMP-0022902-5: RES, 200, 1%, 0.1 W, 0603; Manufacturer: Yageo; Power_W: 100mW; TempCo: 100 ppm/C; Value_Code: 200R; Value: 200; EIA_Code: E96; SizeX_mm: 1.6; SizeY_mm: 0.8; SizeZ_mm: 1; Value2: 0.1W; SizeArea_mm2: 1.28; AEC Qualified: N; VDC_V: 75V; AEC Category: Q200; SizeAreaWB_mm2: 4.68
U5-U8 = CMP-0085241-1: Bidirectional, Precision Low- and High-Side Voltage Output, Current-Sense Amplifier, DRL0006A (SOT-5X3-6); Alternate Manufacturer: Texas Instruments; Alternate PartNumber: INA185A2IDRLR; SizeZ_mm: 0.6; CompType: IC; SizeY_mm: 1.6; SizeAreaWB_mm2: 6.76; AEC Qualified: N; SizeArea_mm2: 2.56; AEC Category: Q200

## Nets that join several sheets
3V3: DRV81646DGQ_M0 (D6.2 J10.2 R33.2 TP10.1), DRV81646DGQ (D13.2 D14.2 D15.2 D16.2), DRV81646DGQ_ADC (9 pins)
3V3_MCU: DRV81646DGQ_XDS110 (J11.4), DRV81646DGQ_M0 (12 pins)
GND: DRV81646DGQ_XDS110 (55 pins), DRV81646DGQ_M0 (27 pins), DRV81646DGQ (48 pins), DRV81646DGQ_ADC (13 pins)
VM: DRV81646DGQ_M0 (D18.2 R4.2 R81.2), DRV81646DGQ (18 pins)
BSL_INVOKE: DRV81646DGQ_XDS110 (XDS1.42), DRV81646DGQ_M0 (R32.2 TP8.1 U1.11)
nFAULT: DRV81646DGQ_M0 (J10.4 R33.1 R34.1 TP11.1), DRV81646DGQ (U3.12)
nSCS/IN3: DRV81646DGQ_M0 (J10.10 TP12.1), DRV81646DGQ (U3.8)
RSLEW/CNTL: DRV81646DGQ_M0 (J10.14 TP9.1), DRV81646DGQ (U3.11)
RST: DRV81646DGQ_XDS110 (J11.10), DRV81646DGQ_M0 (5 pins)
SCLK/IN2: DRV81646DGQ_M0 (J10.8 TP15.1), DRV81646DGQ (U3.7)
SDI/IN1: DRV81646DGQ_M0 (J10.6 TP13.1), DRV81646DGQ (U3.6)
SDO/IN4: DRV81646DGQ_M0 (J10.12 R74.1 TP14.1), DRV81646DGQ (U3.9)
SRC1: DRV81646DGQ (R70.2 TP27.1 U3.1), DRV81646DGQ_ADC (R68.1)
SRC1_ADC_MCU: DRV81646DGQ_M0 (U1.14), DRV81646DGQ_ADC (U5.1)
SRC2: DRV81646DGQ (R62.2 TP24.1 U3.2), DRV81646DGQ_ADC (R60.1)
SRC2_ADC_MCU: DRV81646DGQ_M0 (U1.15), DRV81646DGQ_ADC (U6.1)
SRC3: DRV81646DGQ (R67.2 TP28.1 U3.24), DRV81646DGQ_ADC (R65.1)
SRC3_ADC_MCU: DRV81646DGQ_M0 (U1.16), DRV81646DGQ_ADC (U7.1)
SRC4: DRV81646DGQ (R73.2 TP29.1 U3.23), DRV81646DGQ_ADC (R71.1)
SRC4_ADC_MCU: DRV81646DGQ_M0 (U1.19), DRV81646DGQ_ADC (U8.1)
SWCLK: DRV81646DGQ_XDS110 (J11.14), DRV81646DGQ_M0 (U1.13)
SWDIO: DRV81646DGQ_XDS110 (J11.12), DRV81646DGQ_M0 (U1.12)
UART1_RX: DRV81646DGQ_XDS110 (J11.6), DRV81646DGQ_M0 (U1.53)
UART1_TX: DRV81646DGQ_XDS110 (J11.8), DRV81646DGQ_M0 (U1.52)

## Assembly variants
DRV81646DGQ: not fitted C53 C54 C55 C56 D8 D8 D9 D10 D11 D12 J12 J13 R36 R37 R39 R41 R44 R50 R51 Y1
